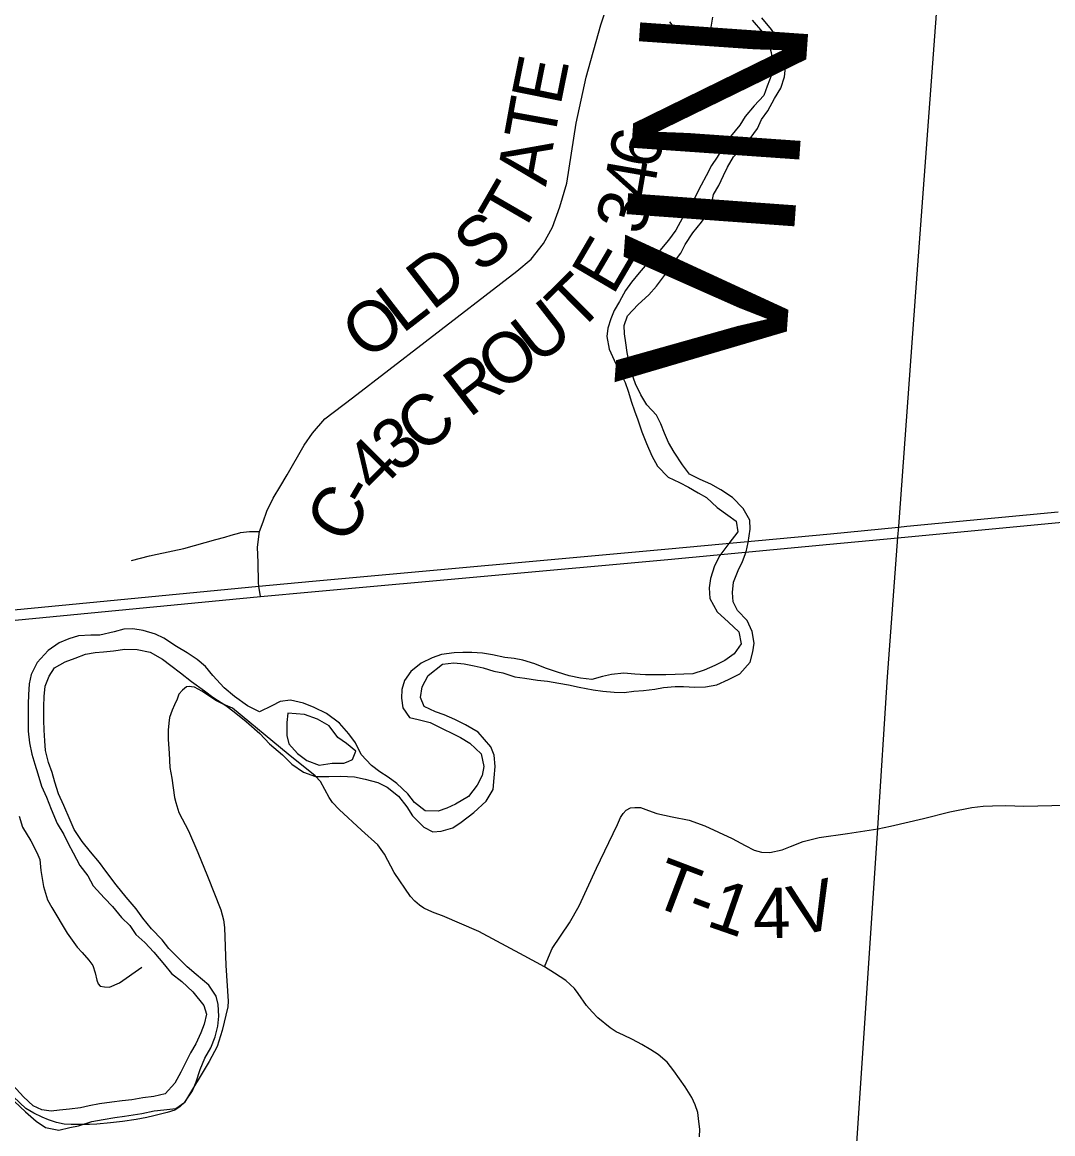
# Model space of a CAD drawing. Extents: x -15 to 405, y -40 to 87.
# Drawn here: x -12.971 to -11.81, y 26.393 to 27.645 of the extents above; entities that cross this region are included whole.
import ezdxf

# ---------------------------------------------------------------- set-up
doc = ezdxf.new("R2010")
doc.units = 0
for name, color, linetype in [('GM_P_State_Location', 7, 'Continuous'), ('GM_P_US_Location', 7, 'Continuous'), ('GM_X_County_Road_Text', 7, 'Continuous'), ('GM_X_Minor_Lake', 7, 'Continuous'), ('GM_X_Minor_River', 7, 'Continuous'), ('GM_X_State_Location', 7, 'Continuous'), ('GM_X_Township_Road', 7, 'Continuous'), ('GM_X_Township_Text', 7, 'Continuous')]:
    doc.layers.add(name, color=color, linetype=linetype)

msp = doc.modelspace()

# ---------------------------------------------------------------- linework, layer by layer
at = {"layer": 'GM_P_State_Location'}
for points in [[(-12.8476, 27.0388), (-12.8274, 27.044), (-12.819, 27.0458), (-12.7889, 27.0522), (-12.7527, 27.0625), (-12.7427, 27.0652), (-12.7354, 27.0675), (-12.7257, 27.0701)], [(-12.7257, 27.0701), (-12.725, 27.0703), (-12.7147, 27.0713), (-12.7038, 27.0714)], [(-12.2082, 26.3901), (-12.2079, 26.3985), (-12.209, 26.4074), (-12.2102, 26.4174), (-12.2129, 26.4261), (-12.2169, 26.4344), (-12.2244, 26.4462), (-12.2369, 26.4643), (-12.2445, 26.4742), (-12.2546, 26.4826), (-12.2631, 26.488), (-12.2733, 26.4939), (-12.2835, 26.4994), (-12.2936, 26.5043), (-12.3021, 26.5081), (-12.3089, 26.5125), (-12.3227, 26.5238), (-12.3291, 26.5305), (-12.3354, 26.5378), (-12.3448, 26.5513), (-12.3491, 26.5571), (-12.3587, 26.5661), (-12.3715, 26.5744), (-12.3827, 26.5815), (-12.4057, 26.5938), (-12.4568, 26.6213), (-12.4974, 26.6388), (-12.507, 26.6423), (-12.5131, 26.6446), (-12.5187, 26.6473), (-12.5236, 26.6507), (-12.5286, 26.6551), (-12.5337, 26.6606), (-12.5521, 26.6876), (-12.5629, 26.7082), (-12.5704, 26.7186), (-12.5886, 26.7353), (-12.614, 26.7584), (-12.6215, 26.7662), (-12.6253, 26.7718), (-12.6351, 26.7901), (-12.6409, 26.7965), (-12.6714, 26.8209), (-12.7144, 26.8564), (-12.7341, 26.8725), (-12.7447, 26.877), (-12.752, 26.8807), (-12.7684, 26.8918), (-12.7768, 26.8962), (-12.78, 26.8964), (-12.7822, 26.897), (-12.7859, 26.8964), (-12.7905, 26.893), (-12.7943, 26.8883), (-12.7964, 26.8828), (-12.7993, 26.8764), (-12.8018, 26.8703), (-12.8048, 26.8619), (-12.8056, 26.8558), (-12.8063, 26.8477), (-12.8063, 26.8371), (-12.8053, 26.822), (-12.8044, 26.8057), (-12.8024, 26.7938), (-12.7995, 26.7721), (-12.798, 26.7665), (-12.7943, 26.7552), (-12.7835, 26.7343), (-12.7731, 26.7102), (-12.7623, 26.6833), (-12.7473, 26.6455), (-12.7443, 26.6342), (-12.7431, 26.6258), (-12.7415, 26.5828), (-12.7388, 26.5427), (-12.7391, 26.5365), (-12.7455, 26.5095), (-12.7513, 26.4918), (-12.7603, 26.4749), (-12.788, 26.4285), (-12.7929, 26.4241), (-12.7989, 26.4201), (-12.8076, 26.4174), (-12.8225, 26.4135), (-12.8303, 26.4117), (-12.8425, 26.4096), (-12.8579, 26.4071), (-12.8712, 26.4056), (-12.8867, 26.4042), (-12.895, 26.4039), (-12.9062, 26.4039), (-12.9158, 26.4038), (-12.9235, 26.4044), (-12.9323, 26.4062), (-12.9413, 26.4091), (-12.9485, 26.412), (-12.9576, 26.4166), (-12.9668, 26.4219), (-12.9807, 26.4349)], [(-12.3827, 26.5815), (-12.3781, 26.5922), (-12.3741, 26.6018), (-12.3547, 26.6309), (-12.3435, 26.6502), (-12.3242, 26.6924), (-12.3104, 26.7214), (-12.3006, 26.7415), (-12.2972, 26.7495), (-12.294, 26.754), (-12.2908, 26.7577), (-12.2859, 26.7604), (-12.281, 26.7609), (-12.2745, 26.7608), (-12.2656, 26.7575), (-12.2563, 26.754), (-12.2389, 26.7501), (-12.2197, 26.7466), (-12.2022, 26.74), (-12.1715, 26.7259), (-12.1568, 26.7181), (-12.1467, 26.7128), (-12.1385, 26.7104), (-12.1291, 26.7101), (-12.115, 26.7131), (-12.1059, 26.7168), (-12.0915, 26.7224), (-12.0795, 26.7255), (-12.0733, 26.7268), (-12.0414, 26.7313), (-12.0075, 26.7368)], [(-12.0075, 26.7368), (-11.9931, 26.7398), (-11.9558, 26.7484), (-11.9262, 26.7558), (-11.9016, 26.7609), (-11.8886, 26.7622), (-11.8784, 26.7626), (-11.8634, 26.763), (-11.8429, 26.7622), (-11.8113, 26.7628), (-11.7908, 26.7636)], [(-12.9741, 26.7509), (-12.9705, 26.7387), (-12.9612, 26.7231), (-12.9542, 26.7099), (-12.951, 26.7023), (-12.9497, 26.6899), (-12.947, 26.6719), (-12.9422, 26.6567), (-12.9374, 26.6483), (-12.92, 26.6193), (-12.9088, 26.6035), (-12.9034, 26.5975), (-12.8956, 26.5887), (-12.8914, 26.5829), (-12.8886, 26.5745), (-12.8868, 26.5663), (-12.8854, 26.5621), (-12.8829, 26.5594), (-12.878, 26.5587), (-12.8726, 26.5583), (-12.8614, 26.5635), (-12.836, 26.5809)]]:
    msp.add_lwpolyline(points, dxfattribs=at)
at = {"layer": 'GM_X_County_Road_Text'}
msp.add_lwpolyline([(-11.8158, 29.5981), (-11.829, 29.4908), (-11.8529, 29.085), (-11.8796, 28.688), (-11.8901, 28.5317), (-11.9037, 28.329), (-11.9193, 28.0402), (-11.9394, 27.7533), (-11.9393, 27.6849), (-11.9648, 27.3408), (-11.9842, 27.077), (-11.9851, 27.0649), (-11.9967, 26.9077), (-12.0077, 26.7373), (-12.0327, 26.366)], dxfattribs=at)
at = {"layer": 'GM_X_State_Location'}
for points in [[(-11.9849, 27.0644), (-11.7999, 27.0819), (-11.6754, 27.0932), (-11.6103, 27.0991), (-11.5834, 27.1025), (-11.5696, 27.1054), (-11.5481, 27.1092), (-11.5089, 27.1206), (-11.4686, 27.1378), (-11.4396, 27.154), (-11.4129, 27.1725), (-11.3582, 27.219), (-11.2411, 27.3225), (-11.1901, 27.3686), (-11.1173, 27.4327), (-11.0928, 27.4528), (-11.0687, 27.4711), (-11.0491, 27.4857), (-11.0129, 27.5101), (-10.9897, 27.5253), (-10.9625, 27.5412), (-10.8197, 27.6263), (-10.7247, 27.6824)], [(-11.984, 27.0765), (-11.9748, 27.0773), (-11.8042, 27.0935)], [(-13.0311, 26.9784), (-12.8866, 26.9923), (-12.7042, 27.0099), (-12.644, 27.0155), (-12.2429, 27.052), (-12.0605, 27.069), (-11.984, 27.0765)], [(-13.0296, 26.9667), (-12.8851, 26.9806), (-12.7026, 26.9981), (-12.6449, 27.0034), (-12.2438, 27.0399), (-12.0614, 27.057), (-11.9849, 27.0644)]]:
    msp.add_lwpolyline(points, dxfattribs=at)
at = {"layer": 'GM_X_Township_Road'}
for points in [[(-12.1488, 27.647), (-12.1374, 27.6334), (-12.1309, 27.6235), (-12.1275, 27.6106), (-12.1253, 27.5969), (-12.1268, 27.5863), (-12.1321, 27.5727), (-12.1356, 27.5624), (-12.1466, 27.5507), (-12.1568, 27.5385), (-12.1629, 27.529), (-12.1732, 27.5161), (-12.1819, 27.5036), (-12.1884, 27.493), (-12.1945, 27.4835), (-12.2006, 27.4718), (-12.2063, 27.4615), (-12.2139, 27.4467), (-12.2196, 27.4373), (-12.2272, 27.4244), (-12.2348, 27.4107), (-12.2432, 27.3993), (-12.2527, 27.3876), (-12.2671, 27.3732), (-12.2763, 27.3625), (-12.2846, 27.3523), (-12.2915, 27.3428), (-12.2983, 27.3303), (-12.3044, 27.3204), (-12.3082, 27.311), (-12.3113, 27.3003), (-12.3124, 27.2909), (-12.3098, 27.2768), (-12.3041, 27.2643), (-12.2976, 27.2506), (-12.292, 27.2392), (-12.2886, 27.2294), (-12.2848, 27.2172), (-12.2814, 27.2073), (-12.2776, 27.1971), (-12.273, 27.1838), (-12.2677, 27.1705), (-12.2617, 27.1565), (-12.2556, 27.1451), (-12.2435, 27.1326), (-12.2306, 27.1265), (-12.2207, 27.1215), (-12.2097, 27.1151), (-12.2002, 27.1098), (-12.1884, 27.0984), (-12.1763, 27.09), (-12.1668, 27.0832), (-12.1649, 27.071), (-12.1752, 27.0581), (-12.1851, 27.0445), (-12.1912, 27.0327), (-12.1957, 27.0187), (-12.1973, 27.0081), (-12.1965, 26.9959), (-12.1882, 26.9811), (-12.1757, 26.9693), (-12.1639, 26.9583), (-12.1613, 26.945), (-12.1692, 26.9337), (-12.1795, 26.9261), (-12.1909, 26.9204), (-12.2031, 26.9155), (-12.2156, 26.9113), (-12.2258, 26.9109), (-12.2357, 26.9106), (-12.246, 26.9102), (-12.2691, 26.9102), (-12.2809, 26.911), (-12.2934, 26.9121), (-12.3071, 26.9106), (-12.3174, 26.9083), (-12.3295, 26.9049), (-12.342, 26.9065), (-12.355, 26.9088), (-12.3682, 26.9129), (-12.3815, 26.9175), (-12.3937, 26.9224)], [(-12.3667, 26.9008), (-12.3557, 26.8989), (-12.3436, 26.8962), (-12.328, 26.8932), (-12.317, 26.8917), (-12.3041, 26.8905), (-12.2931, 26.8901), (-12.2821, 26.8916), (-12.2711, 26.8924), (-12.2585, 26.8939), (-12.2486, 26.8958), (-12.2357, 26.8969), (-12.2262, 26.8969), (-12.2133, 26.8961), (-12.2016, 26.8965), (-12.1886, 26.8988), (-12.1754, 26.9048), (-12.1628, 26.9113), (-12.151, 26.9245), (-12.148, 26.9359), (-12.1468, 26.9458), (-12.1487, 26.9587), (-12.1544, 26.9712), (-12.1654, 26.9826), (-12.1703, 26.9921), (-12.1711, 27.0027), (-12.1699, 27.0145), (-12.1646, 27.0274), (-12.1596, 27.0376), (-12.1555, 27.0486), (-12.1532, 27.0589), (-12.1513, 27.0741), (-12.1516, 27.0843), (-12.1592, 27.0972), (-12.171, 27.1097), (-12.1842, 27.1185), (-12.1953, 27.1246), (-12.2074, 27.1299), (-12.2195, 27.136), (-12.2275, 27.1466), (-12.2366, 27.1606), (-12.243, 27.1716), (-12.2476, 27.1823), (-12.2518, 27.1925), (-12.2567, 27.2024), (-12.2673, 27.2142), (-12.2741, 27.2252), (-12.2802, 27.2377), (-12.2844, 27.2495), (-12.287, 27.2597), (-12.2896, 27.273), (-12.2912, 27.284), (-12.2927, 27.2939), (-12.293, 27.3034), (-12.2892, 27.3144), (-12.2774, 27.3269), (-12.2653, 27.3379), (-12.2565, 27.3477), (-12.2463, 27.361), (-12.239, 27.372), (-12.2292, 27.3849), (-12.2242, 27.3944), (-12.2158, 27.4077), (-12.206, 27.4198), (-12.1983, 27.43), (-12.1945, 27.4399), (-12.1923, 27.4509), (-12.1865, 27.4608), (-12.1812, 27.4721), (-12.1767, 27.4816), (-12.1698, 27.4934), (-12.1607, 27.5029), (-12.1512, 27.5139), (-12.1428, 27.5252), (-12.1382, 27.5351), (-12.1314, 27.545), (-12.1238, 27.559), (-12.1166, 27.5704), (-12.1124, 27.5833), (-12.1112, 27.5943), (-12.1123, 27.6079), (-12.1188, 27.6239), (-12.1271, 27.6364), (-12.1381, 27.6497)], [(-12.2418, 27.6452), (-12.2316, 27.6315), (-12.2187, 27.622), (-12.205, 27.6247), (-12.1955, 27.6368), (-12.1932, 27.6505)], [(-12.3937, 26.9224), (-12.407, 26.9266), (-12.4168, 26.9285), (-12.4275, 26.9297), (-12.4411, 26.9327), (-12.4525, 26.9343), (-12.4647, 26.9354), (-12.4745, 26.9354), (-12.4844, 26.9347), (-12.4988, 26.9328), (-12.5091, 26.9294), (-12.5216, 26.9233), (-12.5334, 26.9138), (-12.5403, 26.9036), (-12.5433, 26.8937), (-12.5437, 26.8839), (-12.5422, 26.8728), (-12.5346, 26.8622), (-12.5251, 26.8599), (-12.5114, 26.8565), (-12.4966, 26.8489), (-12.4872, 26.8443), (-12.4773, 26.8394), (-12.4667, 26.8333), (-12.4541, 26.8212), (-12.4511, 26.8067), (-12.453, 26.7969), (-12.4587, 26.7859), (-12.4682, 26.773), (-12.4831, 26.7646), (-12.4926, 26.7601), (-12.5024, 26.7567), (-12.5169, 26.7571), (-12.529, 26.7662), (-12.5366, 26.7761), (-12.5491, 26.7878), (-12.5586, 26.7947), (-12.5681, 26.8008), (-12.5776, 26.808), (-12.5893, 26.8205), (-12.5954, 26.8334), (-12.603, 26.8437), (-12.6136, 26.8558), (-12.628, 26.8665), (-12.6421, 26.8733), (-12.6542, 26.8782), (-12.6686, 26.8817), (-12.6804, 26.8802), (-12.6899, 26.8752), (-12.7036, 26.8684), (-12.7172, 26.8753), (-12.7317, 26.8855), (-12.7434, 26.8954), (-12.7563, 26.9094), (-12.7643, 26.9193), (-12.7738, 26.9273), (-12.7851, 26.9349), (-12.7969, 26.9421), (-12.8113, 26.9512), (-12.8208, 26.9558), (-12.8345, 26.96), (-12.8462, 26.9619), (-12.8565, 26.9615), (-12.8671, 26.9585), (-12.8835, 26.9547), (-12.8937, 26.9547), (-12.9074, 26.954), (-12.9184, 26.9505), (-12.929, 26.946), (-12.9416, 26.9373), (-12.9541, 26.924), (-12.9606, 26.9104), (-12.9629, 26.9001), (-12.9637, 26.8876), (-12.964, 26.8773), (-12.9641, 26.8466), (-12.9626, 26.8337), (-12.9599, 26.8208), (-12.9565, 26.8094), (-12.9531, 26.7988), (-12.9489, 26.7847), (-12.9436, 26.7722), (-12.9383, 26.7589), (-12.9315, 26.7426), (-12.9239, 26.7304), (-12.919, 26.7202), (-12.9133, 26.7096), (-12.9058, 26.6955), (-12.897, 26.6837), (-12.891, 26.6727), (-12.8781, 26.6587), (-12.869, 26.6492), (-12.8591, 26.637), (-12.8496, 26.6279), (-12.8428, 26.6177), (-12.8326, 26.6086), (-12.8227, 26.5979), (-12.8106, 26.5835), (-12.8026, 26.574), (-12.7912, 26.5649), (-12.7787, 26.5531)], [(-12.7506, 26.5144), (-12.7495, 26.5258), (-12.7502, 26.5391), (-12.7525, 26.5485), (-12.7605, 26.5607), (-12.7749, 26.5728), (-12.7851, 26.5812), (-12.7946, 26.5907), (-12.8056, 26.6021), (-12.8132, 26.6116), (-12.8253, 26.6241), (-12.8348, 26.6363), (-12.8424, 26.6465), (-12.8538, 26.6598), (-12.8651, 26.6735), (-12.8765, 26.689), (-12.8837, 26.6989), (-12.894, 26.7107), (-12.9031, 26.7225), (-12.9122, 26.7358), (-12.9167, 26.7464), (-12.9239, 26.7631), (-12.93, 26.776), (-12.9341, 26.7893), (-12.9372, 26.8003), (-12.9413, 26.8113), (-12.9444, 26.825), (-12.9455, 26.8356), (-12.9462, 26.8477), (-12.9466, 26.8591), (-12.9466, 26.8743), (-12.9462, 26.8857), (-12.945, 26.8974), (-12.9405, 26.9084), (-12.9344, 26.9179), (-12.9226, 26.9247), (-12.9112, 26.9289), (-12.8994, 26.9335), (-12.8888, 26.9353), (-12.8793, 26.9361), (-12.8679, 26.9372), (-12.8554, 26.9391), (-12.8413, 26.9387), (-12.8269, 26.9357), (-12.8129, 26.9277), (-12.8034, 26.9205), (-12.7924, 26.9125), (-12.7802, 26.9026), (-12.7654, 26.892), (-12.756, 26.8848), (-12.7415, 26.8757), (-12.732, 26.8684), (-12.7188, 26.8574), (-12.7032, 26.8441), (-12.6922, 26.8324), (-12.6778, 26.8202), (-12.6672, 26.8096), (-12.6539, 26.8004), (-12.6406, 26.7955), (-12.6254, 26.7955), (-12.6125, 26.7959), (-12.5966, 26.7951), (-12.5848, 26.7928), (-12.5704, 26.789), (-12.5597, 26.7837), (-12.5472, 26.7734), (-12.5377, 26.7613), (-12.5313, 26.7514), (-12.5184, 26.7385), (-12.5085, 26.7335), (-12.499, 26.7339), (-12.4861, 26.7377), (-12.4766, 26.7442), (-12.4622, 26.7551), (-12.4485, 26.768), (-12.4405, 26.7809), (-12.4394, 26.7942), (-12.4382, 26.8067), (-12.4393, 26.8196), (-12.4431, 26.8291), (-12.4575, 26.8455), (-12.4716, 26.8538), (-12.4837, 26.8599), (-12.4955, 26.8652), (-12.5054, 26.8686), (-12.5183, 26.8743), (-12.5224, 26.8846), (-12.5205, 26.8964), (-12.5137, 26.9093), (-12.4977, 26.9221), (-12.4848, 26.9237), (-12.473, 26.9225), (-12.462, 26.9202), (-12.4518, 26.9179), (-12.4396, 26.9141), (-12.4298, 26.9122), (-12.4161, 26.908), (-12.4047, 26.9065), (-12.3906, 26.9042), (-12.3793, 26.9031), (-12.3667, 26.9008)], [(-12.6718, 26.8669), (-12.6729, 26.8566), (-12.6729, 26.8419), (-12.6706, 26.8324), (-12.6607, 26.8214), (-12.6505, 26.8138), (-12.6365, 26.8082), (-12.6217, 26.8105), (-12.6088, 26.8105), (-12.6037, 26.8126)], [(-12.6037, 26.8126), (-12.599, 26.8147), (-12.5952, 26.8241), (-12.6058, 26.8328), (-12.6153, 26.8397), (-12.6252, 26.8525), (-12.6384, 26.8601), (-12.6528, 26.8654), (-12.6718, 26.8669)], [(-12.7787, 26.5531), (-12.7662, 26.5379), (-12.7632, 26.5281), (-12.7658, 26.5167), (-12.7696, 26.5072), (-12.7753, 26.4947), (-12.7814, 26.4844), (-12.7871, 26.4734), (-12.7921, 26.4628), (-12.7989, 26.4503), (-12.8099, 26.4385), (-12.8225, 26.4355), (-12.835, 26.434), (-12.8472, 26.4317), (-12.8582, 26.4306), (-12.87, 26.4291), (-12.8836, 26.4272), (-12.8954, 26.4249), (-12.9053, 26.4227), (-12.9174, 26.4212), (-12.9288, 26.42), (-12.9383, 26.4189), (-12.9486, 26.4204), (-12.9584, 26.425), (-12.9694, 26.4349), (-12.9812, 26.4481)], [(-12.9793, 26.4299), (-12.9672, 26.4182), (-12.955, 26.4075), (-12.9444, 26.4003), (-12.9296, 26.3976), (-12.9171, 26.4003), (-12.9076, 26.4025), (-12.8924, 26.4071), (-12.8795, 26.4094), (-12.8666, 26.4116), (-12.8555, 26.4131), (-12.8457, 26.4146), (-12.8362, 26.4162), (-12.8221, 26.4192), (-12.8115, 26.4203), (-12.7978, 26.4218), (-12.7876, 26.429), (-12.7792, 26.4419), (-12.775, 26.4518), (-12.7704, 26.4658), (-12.7651, 26.4787), (-12.7583, 26.4901), (-12.7537, 26.5026), (-12.7506, 26.5144)]]:
    msp.add_lwpolyline(points, dxfattribs=at)
at = {"layer": 'GM_X_Township_Text'}
for points in [[(-12.6735, 27.1335), (-12.6725, 27.1352), (-12.6532, 27.1687), (-12.6441, 27.1822), (-12.6302, 27.1982), (-12.5988, 27.222), (-12.5169, 27.2849), (-12.4139, 27.3645), (-12.3979, 27.3781), (-12.384, 27.3956), (-12.3737, 27.4141), (-12.3655, 27.4369), (-12.3577, 27.4637), (-12.3497, 27.5144), (-12.3469, 27.531), (-12.3357, 27.5831), (-12.3192, 27.6418), (-12.3076, 27.6775), (-12.2978, 27.7057), (-12.2912, 27.7207), (-12.2762, 27.7419)], [(-12.7026, 26.9981), (-12.7042, 27.0099), (-12.7046, 27.0135), (-12.7052, 27.0367), (-12.7057, 27.0539), (-12.7038, 27.0714), (-12.6996, 27.0823), (-12.6952, 27.0943), (-12.6883, 27.109), (-12.6796, 27.1231), (-12.6735, 27.1335)]]:
    msp.add_lwpolyline(points, dxfattribs=at)

# ---------------------------------------------------------------- texts
at = {"layer": 'GM_P_US_Location'}
for s, rotation, p in [('N', 85.9918, (-12.0973, 27.4695)), ('I', 85.8516, (-12.103, 27.3917)), ('V', 85.8425, (-12.1151, 27.2246))]:
    msp.add_text(s, height=0.1894, rotation=rotation, dxfattribs=at).set_placement(p)
at = {"layer": 'GM_X_Minor_Lake'}
for s, rotation, p in [('E', 78.532, (-12.3648, 27.5498)), ('T', 79.702, (-12.3723, 27.5083)), ('6', 79.576, (-12.2552, 27.478)), ('A', 79.8433, (-12.3811, 27.4591)), ('4', 80.1171, (-12.2612, 27.4437)), ('T', 59.9468, (-12.4098, 27.4022)), ('3', 73.9149, (-12.2724, 27.4035)), ('S', 38.0351, (-12.4555, 27.3608)), ('E', 59.5716, (-12.3057, 27.3361)), ('D', 37.7427, (-12.5091, 27.3193)), ('T', 44.7663, (-12.3457, 27.2935)), ('L', 37.7442, (-12.5427, 27.2933)), ('O', 37.7501, (-12.5822, 27.2626)), ('U', 37.9327, (-12.3907, 27.2579)), ('O', 37.7167, (-12.4304, 27.2272)), ('R', 37.6583, (-12.4674, 27.1986)), ('C', 37.5943, (-12.5215, 27.1573)), ('3', 37.7317, (-12.5491, 27.1359)), ('4', 45.1545, (-12.5723, 27.1124)), ('C', 60.8089, (-12.6046, 27.0549)), ('-', 59.2558, (-12.582, 27.0953))]:
    msp.add_text(s, height=0.0568, rotation=rotation, dxfattribs=at).set_placement(p)
at = {"layer": 'GM_X_Minor_River'}
for s, rotation, p in [('T', 339.2062, (-12.2652, 26.6519)), ('V', 12.9473, (-12.0997, 26.6153)), ('1', 340.7776, (-12.2021, 26.628)), ('4', 1.1403, (-12.1474, 26.6131)), ('-', 339.3769, (-12.2253, 26.6368))]:
    msp.add_text(s, height=0.0568, rotation=rotation, dxfattribs=at).set_placement(p)

doc.saveas('drawing.dxf')
